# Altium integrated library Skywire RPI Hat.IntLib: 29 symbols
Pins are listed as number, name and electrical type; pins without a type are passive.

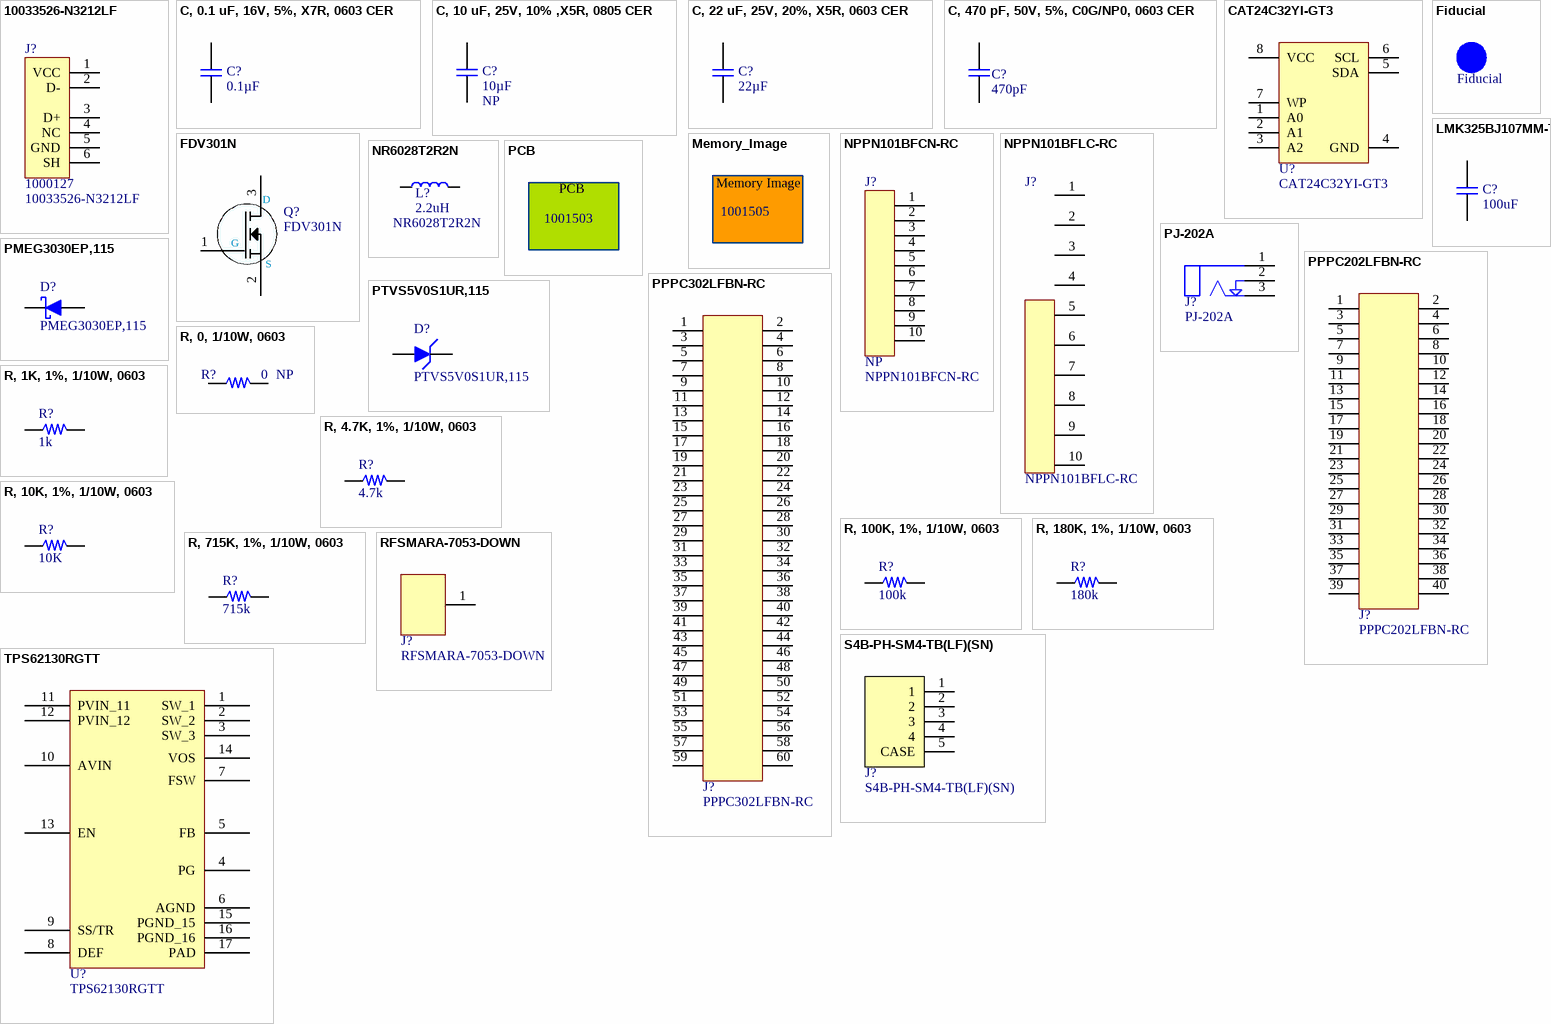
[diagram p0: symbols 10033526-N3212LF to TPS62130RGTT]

## 10033526-N3212LF
designator J?, comment Part_Number: 1000127  Manufacturer_Part_Number1: 10033526-N3212LF  (hidden comment: USB MINI B)
Connector, USB, Mini B, Right Angle, SMD; Manufacturer1: Amphenol; Gender: Receptacle; Item_Phase: Production; Connector_Type: USB - mini B; Mounting_Type: Surface Mount Right Angle Horizontal; Number_of_Pins: 5
footprint 10033526-N3212LF
pins: 1 VCC, 2 D-, 3 D+, 4 NC, 5 GND, 6 SH

## C, 0.1 uF, 16V, 5%, X7R, 0603 CER
designator C?, comment Capacitance: 0.1µF  (hidden comment: 1000755)
Capacitor, 0.1 uF, 16V, 5%, X7R, 0603; Manufacturer1: Samsung Electro-Mechanics America, Inc; Manufacturer_Part_Number1: CL10B104JO8NNNC; Item_Phase: Production; Capacitor_Type: Ceramic; Mounting_Type: Surface Mount; Operating_Temperature: -55°C ~ 125°C; Thickness_Max: 0.035" (0.90mm)
footprint 0603
pins: 1, 2

## C, 10 uF, 25V, 10% ,X5R, 0805 CER
designator C?, comment Capacitance: 10µF  Population: NP  (hidden comment: 1000780)
Capacitor, 10 uF, 25V, 10%, X5R, 0805; Manufacturer1: Samsung Electro-Mechanics America, Inc; Manufacturer_Part_Number1: CL21A106KAYNNNE; Item_Phase: Production; Capacitor_Type: Ceramic; Mounting_Type: Surface Mount; Operating_Temperature: -55°C ~ 85°C; Thickness_Max: 0.057" (1.45mm)
footprint 0805
pins: 1, 2

## C, 22 uF, 25V, 20%, X5R, 0603 CER
designator C?  Capacitance: 22µF  (hidden comment: C, 22 uF, 25V, 20%, X5R, 0603 CER)
Capacitor, 22 uF, 25V, 20%, X5R, 0603; Part_Number: 1000932; Manufacturer1: TDK Corporation; Manufacturer_Part_Number1: C1608X5R1A226M080AC; Item_Phase: Production; Capacitor_Type: Ceramic; Mounting_Type: Surface Mount; Operating_Temperature: -55°C ~ 85°C; Thickness_Max: 0.035" (0.90mm); Voltage_Rating: 10V
footprint 0603
pins: 1, 2

## C, 470 pF, 50V, 5%, C0G/NP0, 0603 CER
designator C?  Capacitance: 470pF  (hidden comment: C, 470 pF, 50V, 5%, C0G/NP0, 0603 CER)
Capacitor, 470 pF, 50V, 5%, C0G/NP0, 0603; Part_Number: 1000777; Manufacturer1: Samsung Electro-Mechanics America, Inc; Manufacturer_Part_Number1: CL10C471JB8NCNC; Item_Phase: Production; Capacitor_Type: Ceramic; Mounting_Type: Surface Mount; Operating_Temperature: -55°C ~ 125°C; Temperature_Coefficient: C0G, NP0; Thickness_Max: 0.035" (0.90mm)
footprint 0603
pins: 1, 2

## CAT24C32YI-GT3
designator U?, comment Manufacturer_Part_Number1: CAT24C32YI-GT3  (hidden comment: .)
IC, EEPROM, I2C, 32Kb, 400KHz, 1.7V-5.5V, 8-TSSOP; Part_Number: 1001385; Manufacturer1: ON Semiconductor; Item_Phase: Preliminary; Current_Supply: 2 mA; Mounting_Type: Surface Mount; Operating_Temperature: -40°C ~ 85°C; Voltage_Supply_Max: 5.5V; Voltage_Supply_Min: 1.7V; Voltage_Supply_Typical: 3.3V
footprint TSSOP8 4.4x3 CASE 948AL-01
footprint TSSOP8
pins: 1 A0, 2 A1, 3 A2, 4 GND, 5 SDA, 6 SCL, 7 WP, 8 VCC

## FDV301N
designator Q?, comment Manufacturer_Part_Number1: FDV301N  (hidden comment: 1000512)
Transistor, MOSFET, N-CH, 25V, 0.220mA, SOT-23-3; Manufacturer1: ON Semiconductor; Item_Phase: Production; Mounting_Type: Surface Mount; Transistor_Type: NCH - FET
footprint SOT95P300X115-3N (SOT23, 3-Leads, Body 3.10x3.00mm, Pitch 0.95mm, IPC Medium Density)
pins: 1 G, 2 S, 3 D

## Fiducial
designator Fiducial?
Fiducial, 1mm; Population: NP
footprint Fiducial 1mm

## LMK325BJ107MM-T
designator C?, comment Capacitance: 100uF  (hidden comment: 1001241)
Capacitor. 100uF, 10V, 20%, X5R, 1210; Manufacturer1: Taiyo Yuden; Manufacturer_Part_Number1: LMK325BJ107MM-T; Tolerance: +/- 20%; Item_Phase: Production; Capacitor_Type: Ceramic; Mounting_Type: Surface Mount; Operating_Temperature: -55C ~ +85C; Thickness_Max: 0.106 (2.70mm)"
footprint CAPC3225X25N_1210 (Chip Capacitor, 2-Leads, 1210)
pins: 1, 2

## Memory_Image
designator Memory Image?  Part_Number: 1001505  (hidden comment: Memory_Image)  (mechanical)
Memory Image

## NPPN101BFCN-RC
designator J?, comment Population: NP  Manufacturer_Part_Number1: NPPN101BFCN-RC  (hidden comment: 1000864)
Connector, Header, Female, 2.00mm, 10x1, TH; Manufacturer1: Sullins Connector Solutions; Pitch: 0.079" (2.00mm); Item_Phase: Production; Contact_Finish: Gold; Contact_Type: Female Socket; Mounting_Type: Through Hole; Number_of_Positions: 10; Number_of_Positions_Loaded: All; Number_of_Rows: 1
footprint NPPN101BFCN-RC (Footprint not found)
footprint Socket 2mm 1x10 NP
pins: 1, 2, 3, 4, 5, 6, 7, 8, 9, 10

## NPPN101BFLC-RC
designator J?, comment Manufacturer_Part_Number1: NPPN101BFLC-RC  (hidden comment: 1000865)
Connector, Female, 2.00mm, 10x1, SMD, Left Oriented; Manufacturer1: Sullins Connector Solutions; Item_Phase: Production; Connector_Type: Header; Contact_Finish: Gold; Contact_Type: Female Socket; Current_Rating: 2A; Fastening_Type: Push-Pull; Header_Orientation: Vertical; Insertion_Removal_Method: Push In / Pull Out; Mounting_Type: Surface Mount; Number_of_Pins: 10; Number_of_Rows: 1; Operating_Temperature: -40°C ~ 105°C; Pitch: 0.079" (2.00mm); Voltage_Rating: 150V
footprint NPPN101BFLC-RC (Skywire Footprint with surfacemount pads)
pins: 1, 2, 3, 4, 5, 6, 7, 8, 9, 10

## NR6028T2R2N
designator L?, comment Inductance: 2.2uH  Manufacturer_Part_Number1: NR6028T2R2N  (hidden comment: 1001263)
Inductor, 2.2uH, 3.7A, 30%, 26mOhm, 6.00x6.00mm; Manufacturer1: Taiyo Yuden; Shielding: Shielded; Item_Phase: Production; Current_Saturation: 4.2A; DC_Resistance: 26 mOhm Max; Frequency_Self_Resonant: 68MHz; Frequency_Test: 100kHz; Mounting_Type: Surface Mount; Operating_Temperature: -25°C ~ 120°C; Inductor_Type: Wirewound
footprint NR6028 (Footprint not found)
pins: 1, 2

## PCB
designator PCB?  Part_Number: 1001503  (hidden comment: PCB)  (mechanical)
PCB Part Number

## PJ-202A
designator J?, comment Manufacturer_Part_Number1: PJ-202A  (hidden comment: 1000221)
Connector, Barrel, 24V, 2.5A, 2.1mm ID, 5.5mm OD; Manufacturer1: CUI Inc; Gender: Male; Item_Phase: Production; Connector_Type: Jack; Mounting_Type: Through Hole; Operating_Temperature: -25°C ~ 85°C; Voltage_Rating: 16VDC
footprint PJ-202A (PJ-202A  Barrel Plug)
pins: 1, 2, 3

## PMEG3030EP,115
designator D?, comment Manufacturer_Part_Number1: PMEG3030EP,115  (hidden comment: 1001261)
Diode, Schottky, 30V, 3A, 0.360 Vf, SOD-128; Manufacturer1: NXP Semiconductors; Item_Phase: Production; Current_Reverse_Leakage_at_Vref: 5mA @ 30V; Mounting_Type: Surface Mount; Operating_Temperature: 150°C (Max); Voltage_Forward_VF_Max_at_I_Forward: 360mV @ 3A
footprint SOD128
pins: A, K

## PPPC202LFBN-RC
designator J?, comment Manufacturer_Part_Number1: PPPC202LFBN-RC  (hidden comment: 1001252)
Connector, Header, Female, 2.54mm, 20x2, TH; Manufacturer1: Sullins Connector Solutions; Item_Phase: Production; Contact_Finish: Gold; Contact_Type: Female Socket; Current_Rating: 3A; Fastening_Type: Push-Pull; Mounting_Type: Through Hole; Number_of_Pins: 40; Number_of_Rows: 2; Operating_Temperature: -40C ~ +105C; Pitch: 0.100 (2.54mm)"; Voltage_Rating: 250V
footprint PPPC202LFBN-RC (Footprint not found)
pins: 1, 2, 3, 4, 5, 6, 7, 8, 9, 10, 11, 12, 13, 14, 15, 16, 17, 18, 19, 20, 21, 22, 23, 24, 25, 26, 27, 28, 29, 30, 31, 32, 33, 34, 35, 36, 37, 38, 39, 40

## PPPC302LFBN-RC
designator J?, comment Manufacturer_Part_Number1: PPPC302LFBN-RC  (hidden comment: 1001253)
Connector, Header, Female, 2.54mm, 30x2, TH; Manufacturer1: Sullins Connector Solutions; Item_Phase: Production; Contact_Finish: Gold; Contact_Type: Female Socket; Current_Rating: 3A; Mounting_Type: Through Hole; Number_of_Pins: 60; Number_of_Rows: 2; Operating_Temperature: -40C ~ +105C; Pitch: 0.100 (2.54mm)"; Voltage_Rating: 250V
footprint PPPC302LFBN-RC
pins: 1, 2, 3, 4, 5, 6, 7, 8, 9, 10, 11, 12, 13, 14, 15, 16, 17, 18, 19, 20, 21, 22, 23, 24, 25, 26, 27, 28, 29, 30, 31, 32, 33, 34, 35, 36, 37, 38, 39, 40, 41, 42, 43, 44, 45, 46, 47, 48, 49, 50, 51, 52, 53, 54, 55, 56, 57, 58, 59, 60

## PTVS5V0S1UR,115
designator D?, comment Manufacturer_Part_Number1: PTVS5V0S1UR,115  (hidden comment: 1000501)
Diode, TVS, Unidirectional, 5V, 43.5A, SOD-123W; Manufacturer1: NXP Semiconductors; Item_Phase: Production; Diode_Type: Zener; Mounting_Type: Surface Mount; Operating_Temperature: -55°C ~ 150°C (TA)
footprint SOD123W
pins: A, K

## R, 0, 1/10W, 0603
designator R?, comment Population: NP  (hidden comment: 0)
Resistor, 0, 1/10W, 0603; Part_Number: 1000666; Manufacturer1: Panasonic Electronic Components; Manufacturer_Part_Number1: ERJ-3GEY0R00V; Item_Phase: Production; Mounting_Type: Surface Mount; Number_of_Terminations: 2; Operating_Temperature: -55°C ~ 155°C; Power: 0.1W, 1/10W; Resistor_Package: 0603 (1608 Metric); Tolerance: Jumper
footprint 0603
pins: 1, 2

## R, 1K, 1%, 1/10W, 0603
designator R?  Resistance_Ohms: 1k
Resistor, 1K, 1%, 1/10W, 0603; Part_Number: 1000590; Manufacturer1: Panasonic Electronic Components; Manufacturer_Part_Number1: ERJ-3EKF1001V; Item_Phase: Production; Mounting_Type: Surface Mount; Number_of_Terminations: 2; Operating_Temperature: -55°C ~ 155°C; Power: 0.1W, 1/10W; Resistor_Package: 0603 (1608 Metric); Temperature_Coefficient: ±100ppm/°C
footprint 0603
pins: 1, 2

## R, 4.7K, 1%, 1/10W, 0603
designator R?, comment Resistance_Ohms: 4.7k  (hidden comment: 1000803)
Resistor, 4.7K, 1%, 1/10W, 0603; Manufacturer1: Samsung Electro-Mechanics America, Inc; Manufacturer_Part_Number1: RC1608F472CS; Item_Phase: Production; Mounting_Type: Surface Mount; Number_of_Terminations: 2; Operating_Temperature: -55°C ~ 155°C; Power: 0.1W, 1/10W; Resistor_Package: 0603 (1608 Metric); Temperature_Coefficient: ±100ppm/°C
footprint 0603
pins: 1, 2

## R, 10K, 1%, 1/10W, 0603
designator R?, comment 10K
Resistor, 10K, 1%, 1/10W, 0603; Part_Number: 1000591; Manufacturer1: Panasonic Electronic Components; Manufacturer_Part_Number1: ERJ-3EKF1002V; Item_Phase: Production; Mounting_Type: Surface Mount; Operating_Temperature: - 55 C to + 155 C; Power: 0.1W, 1/10W; Resistor_Package: 0603 (1608 Metric); Temperature_Coefficient: 100 PPM / C
footprint 0603
pins: 1, 2

## R, 100K, 1%, 1/10W, 0603
designator R?, comment 100K
Resistor, 100K, 1%, 1/10W, 0603; Part_Number: 1000799; Manufacturer1: Samsung Electro-Mechanics America, Inc; Manufacturer_Part_Number1: RC1608F104CS; Item_Phase: Production; Mounting_Type: Surface Mount; Number_of_Terminations: 2; Power: 0.1W, 1/10W; Resistor_Package: 0603 (1608 Metric); Temperature_Coefficient: ±100ppm/°C
footprint 0603
pins: 1, 2

## R, 180K, 1%, 1/10W, 0603
designator R?, comment Resistance_Ohms: 180k  (hidden comment: 1001234)
Resistor, 180K, 1%, 1/10W, 0603; Manufacturer1: Yageo; Manufacturer_Part_Number1: RC0603FR-07180KL; Item_Phase: Production; Mounting_Type: Surface Mount; Number_of_Terminations: 2; Operating_Temperature: -55°C ~ 155°C; Power: 0.1W, 1/10W; Resistor_Package: 0603 (1608 Metric); Temperature_Coefficient: ±100ppm/°C
footprint 0603
pins: 1, 2

## R, 715K, 1%, 1/10W, 0603
designator R?, comment 715K
Resistor, 715K, 1%, 1/10W, 0603; Part_Number: 1000656; Manufacturer1: Panasonic Electronic Components; Manufacturer_Part_Number1: ERJ-3EKF7153V; Item_Phase: Production; Mounting_Type: Surface Mount; Number_of_Terminations: 2; Operating_Temperature: -55°C ~ 155°C; Power: 0.1W, 1/10W; Resistor_Package: 0603 (1608 Metric); Temperature_Coefficient: ±100ppm/°C
footprint 0603
pins: 1, 2

## RFSMARA-7053-DOWN
designator J?, comment Manufacturer_Part_Number1: RFSMARA-7053-DOWN  (hidden comment: UFL to SMA)
Connector, ANT, UFL to PCB Mount SMA, UFL Down, 53mm, TH; Part_Number: 1000732; Manufacturer1: ROHO COMMUNICATION TECHNOLOGY CO. Ltd; Item_Phase: Production; Mounting_Type: Other
footprint UFL TO SMA
pins: 1

## S4B-PH-SM4-TB(LF)(SN)
designator J?, comment Manufacturer_Part_Number1: S4B-PH-SM4-TB(LF)(SN)  (hidden comment: 1001260)
Connector, Header, Male, 2.00mm, 4x1, Right Angle, SMD; Manufacturer1: JST Sales America Inc; Pitch: 0.079 (2.00mm)"; Item_Phase: Production; Connector_Type: Header, Shrouded; Contact_Finish: Tin; Contact_Type: Male Pin; Fastening_Type: Detent Lock; Mounting_Type: Surface Mount Right Angle; Number_of_Pins: 4; Number_of_Positions_Loaded: All; Number_of_Rows: 1
footprint S4B-PH-SM4-TB(LF)(SN)
pins: 1, 2, 3, 4, 5 CASE

## TPS62130RGTT
designator U?
IC, Buck, ADJ, 3V-17V , 3A, QFN; Part_Number: 1001036; Manufacturer1: Texas Instruments; Item_Phase: Production; Mounting_Type: Surface Mount; Operating_Temperature: -40°C ~ 85°C; Output_Type: Adjustable
footprint QFN50P300X300X100_HS-17N (QFN, 16-Leads, Body 3.00x3.00mm, Pitch 0.50mm, Thermal Pad 1.78x1.78mm, IPC Medium Density)
pins: 1 SW_1, 2 SW_2, 3 SW_3, 4 PG, 5 FB, 6 AGND, 7 FSW, 8 DEF, 9 SS/TR, 10 AVIN, 11 PVIN_11, 12 PVIN_12, 13 EN, 14 VOS, 15 PGND_15, 16 PGND_16, 17 PAD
